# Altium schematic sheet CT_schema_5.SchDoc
size 236 x 258 mm
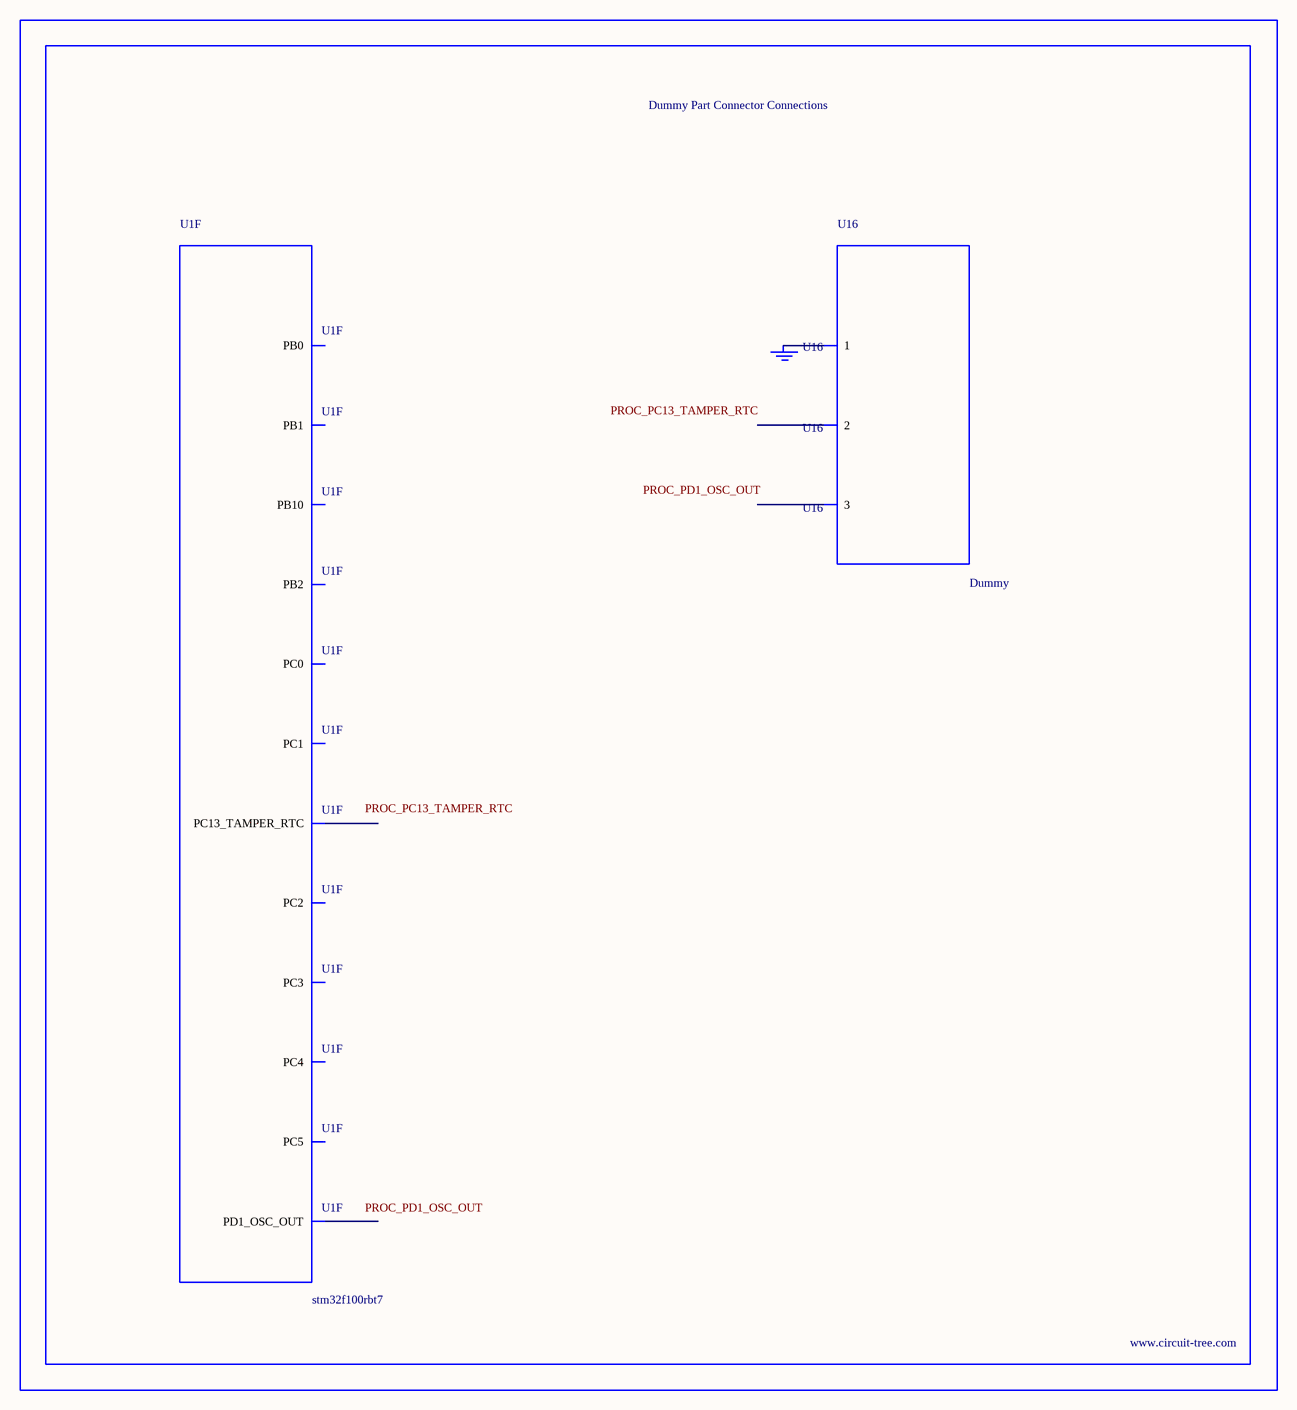
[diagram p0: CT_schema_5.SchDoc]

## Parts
BORDER4  (no value)
GND_INSTANCE_4_0  (no value)
U1  stm32f100rbt7  [LQFP64]  (part F of 6)
U16  Dummy  [DUMMY_PACKAGE_143]

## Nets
NetGND_INSTANCE_4_0_0: GND_INSTANCE_4_0.0(GND) U16.1

Not connected (* = marked no-connect by the designer): U1 2(PC13_TAMPER_RTC) 6(PD1_OSC_OUT) 8(PC0) 9(PC1) 10(PC2) 11(PC3) 24(PC4) 25(PC5) 26(PB0) 27(PB1) 28(PB2) 29(PB10); U16 2 3

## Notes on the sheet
- Labels drawn without touching a wire or pin: PROC_PC13_TAMPER_RTC, PROC_PD1_OSC_OUT

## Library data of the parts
BORDER4 = BORDER_PAGE4
GND_INSTANCE_4_0 = GND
